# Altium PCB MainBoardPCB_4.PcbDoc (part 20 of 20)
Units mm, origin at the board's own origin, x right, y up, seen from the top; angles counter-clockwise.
Board outline 333.63 x 349.38 mm, 16 copper layers (L1, L2 (GND), L3 (Sign), L4 (GND), L5 (Sign), L6 (PWR/GND), L7(PWR/GND), L8 (Plane_GND), L9 (PWR/GND), L10 (PWR/GND), L11 (PWR/GND), L12 (Sign), L13 (GND), L14 (Sign), L15 (GND), L16), stack 2.502 mm thick; 2205 components, 1648 nets, 8314 pads, 3172 vias.
Unrouted connection lines stored in the file: 5141.
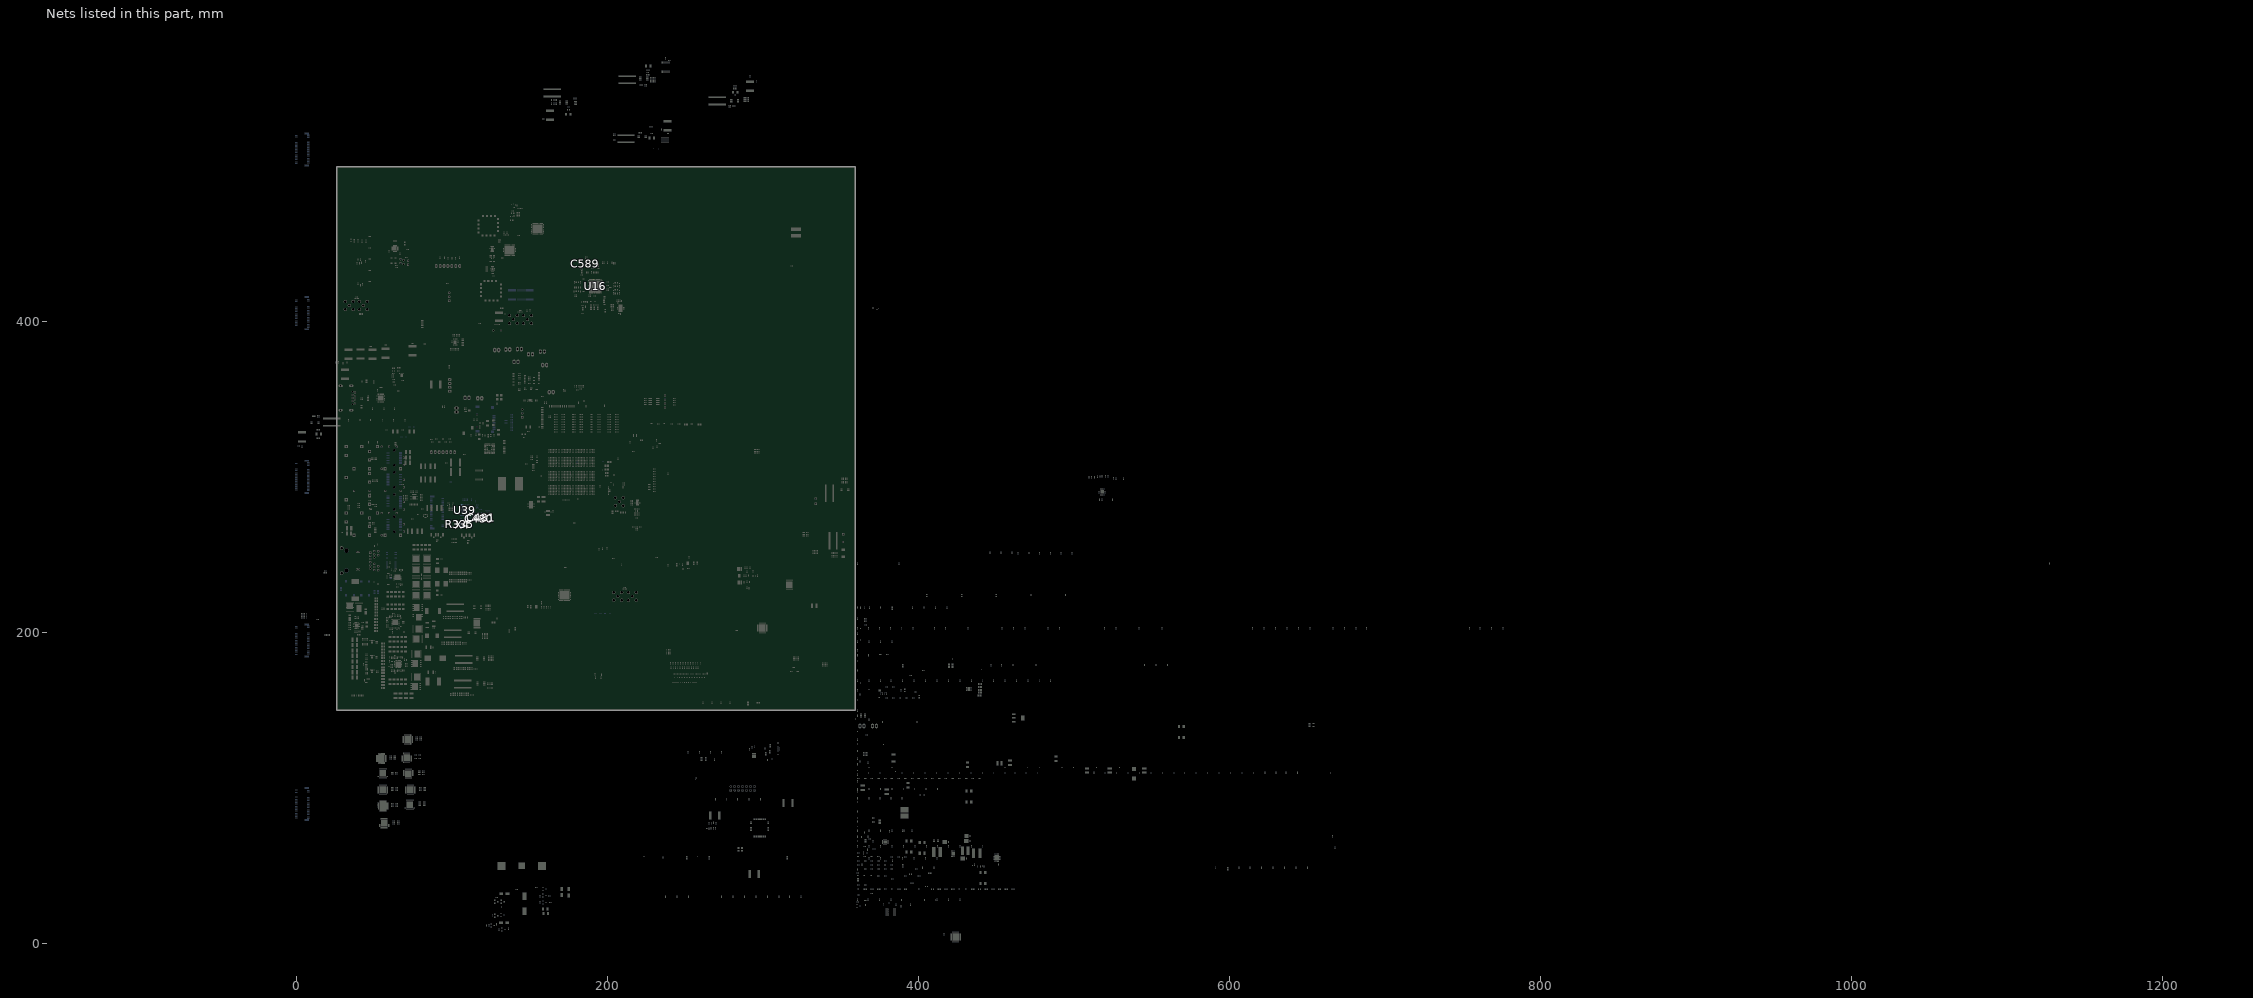
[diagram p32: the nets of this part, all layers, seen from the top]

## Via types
v1: diameter 0.5, hole 0.2, L1 to L16, tented both sides, 1153 vias
v2: diameter 0.5/0.35/0.35/0.35/0.35/0.35/0.35/0.35/0.35/0.35/0.35/0.35/0.35/0.35/0.35/0.5 (per signal layer), hole 0.2, L1 to L16, tented both sides, 548 vias
v3: diameter 0.5, hole 0.2, L1 to L16, 522 vias
v4: diameter 0.5/0.35/0.35/0.35/0.35/0.35/0.35/0.35/0.35/0.35/0.35/0.35/0.35/0.35/0.35/0.5 (per signal layer), hole 0.15, L1 to L16, tented both sides, 266 vias
v5: diameter 0.8, hole 0.4, L1 to L16, tented both sides, 164 vias
v6: diameter 0.35/0/0.35 (per signal layer), hole 0.127, L1 to L3 (Sign), tented both sides, 132 vias
v7: diameter 2.54, hole 1.02, L1 to L16, 125 vias
v8: diameter 1.4, hole 0.5, L1 to L16, tented both sides, 80 vias
v9: diameter 0.35, hole 0.127, L1 to L2 (GND), tented both sides, 36 vias
v10: diameter 0.4, hole 0.2, L1 to L16, 16 vias
v11: diameter 0.25, hole 0.2, L1 to L16, 16 vias
v12: diameter 5, hole 3, L1 to L16, 15 vias
v13: diameter 0.3, hole 0.2, L1 to L16, 15 vias
v14: diameter 0.45, hole 0.15, L1 to L16, 12 vias
v15: diameter 0.5/0.35/0.35/0.35/0.35/0.35/0.35/0.35/0.35/0.35/0.35/0.35/0.35/0.35/0.35/0.45 (per signal layer), hole 0.15, L1 to L16, tented both sides, 10 vias
v16: diameter 0.2/0/0.2 (per signal layer), hole 0.1, L1 to L3 (Sign), tented both sides, 9 vias
v17: diameter 0.4, hole 0.1, L1 to L16, 7 vias
v18: diameter 0.5, hole 0.2, L3 (Sign) to L6 (PWR/GND), tented both sides, 6 vias
v19: diameter 1.65, hole 1.65, L1 to L16, 6 vias
v20: diameter 1.15, hole 1.15, L1 to L16, 6 vias
v21: diameter 0.35/0/0.35 (per signal layer), hole 0.127, L14 (Sign) to L16, tented both sides, 5 vias
v22: diameter 0.2, hole 0.1, L1 to L16, 4 vias
v23: diameter 0.4, hole 0.2, L1 to L16, tented both sides, 2 vias
v24: diameter 0.4, hole 0.15, L1 to L16, 2 vias
v25: diameter 0.508, hole 0.127, L1 to L2 (GND), 2 vias
v26: diameter 0.508, hole 0.127, L2 (GND) to L3 (Sign), 2 vias
v27: diameter 0.5/0.35/0.35/0.35/0.35/0.35/0.35/0.35/0.35/0.35/0.35/0.35/0.35/0.35/0.35/0.5 (per signal layer), hole 0.15, L1 to L16, 2 vias
v28: diameter 0.35, hole 0.127, L3 (Sign) to L6 (PWR/GND), tented both sides, 2 vias
v29: diameter 5.5, hole 3.5, L1 to L16, 1 vias
v30: diameter 0.5/0.35/0.35/0.35/0.35/0.35/0.35/0.35/0.35/0.35/0.35/0.35/0.35/0.35/0.35/0.5 (per signal layer), hole 0.2, L1 to L16, 1 vias
v31: diameter 0.35/0.35/0.35 (per signal layer), hole 0.127, L1 to L3 (Sign), tented both sides, 1 vias
v32: diameter 0.45/0/0.45 (per signal layer), hole 0.15, L1 to L3 (Sign), tented both sides, 1 vias
v33: diameter 0.45/0/0.45 (per signal layer), hole 0.2, L14 (Sign) to L16, tented both sides, 1 vias
v34: diameter 0.35, hole 0.127, L2 (GND) to L3 (Sign), 1 vias
v35: diameter 0.35, hole 0.127, L1 to L2 (GND), 1 vias

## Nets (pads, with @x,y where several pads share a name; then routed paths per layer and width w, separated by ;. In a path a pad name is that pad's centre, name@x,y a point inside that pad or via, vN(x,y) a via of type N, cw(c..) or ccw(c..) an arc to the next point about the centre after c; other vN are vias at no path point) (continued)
X1: C481.2 R335.2 U39.14 X4.1
X2: C480.2 R335.1 U39.15 X4.3
XO_LMK05028_P: C589.2 U16.43
pads on no net: C558.4 D22.2 D28.1 J1_PCIE0. J1_PCIE0.56 J1_PCIE0.58 J1_PCIE1. J1_PCIE1.56 J1_PCIE1.58 J1_PCIE2. J1_PCIE2.56 J1_PCIE2.58 J1_PCIE3. J1_PCIE3.56 J1_PCIE3.58 J1_PCIE4. J1_PCIE4.56 J1_PCIE4.58 J14.3 J27. J27.5 J27.6 J27.7 J27.8 J27.11 J27.13 J27.17 J27.19 J27.20 J27.22 J27.23 J27.24 J27.25 J27.26 J27.28 J27.30 J27.32 J27.34 J27.36 J27.40 J27.42 J27.44 J27.46 J27.48 J27.56 J27.58 J27.59 J28.MH1 J28.MH2 J31. J31.1 J31.2 J31.3 J31.4 J31.5 J31.6 J31.7 J31.8 J31.9 J31.10 J31.11 J31.12 J31.13 J31.14 J31.15 J31.16 J31.17 J31.18 J31.19 J31.20 J31.21 J31.22 J31.23 J31.24 J31.25 J31.26 J31.27 J31.28 J31.29 J31.30 J31.31 J31.32 J31.33 J31.34 J31.35 J31.36 J31.37 J31.38 J31.39 J31.40 J31.41 J31.42 J31.43 J31.44 J31.45 J31.46 J31.47 J31.48 J31.49 J31.50 J31.51 J31.52 J31.53 J31.54 J31.55 J31.56 J31.57 J31.58 J31.59 J31.60 J31.61 J31.62 J31.63 J31.64 J31.65 J31.66 J31.67 J31.68 J31.69 J31.70 J31.71 J31.72 J31.73 J31.74 J31.75 J31.76 J31.77 J31.78 J31.79 J31.80 P12.11 R100.1 R100.2 R132.2 R133.2 R134.2 R135.2 R136.2 R137.2 R138.2 R141.2 R142.2 R145.2 R146.2 R147.2 R148.2 R151.2 R152.2 R455_1.1 R455_1.2 R456_1.1 R456_1.2 R458_1.1 R458_1.2 R460_1.1 R460_1.2 R462_1.1 R462_1.2 R464_1.1 R464_1.2 R475_1.1 R475_1.2 R476_1.1 R476_1.2 R477_1.1 R477_1.2 R478_1.1 R478_1.2 R479_1.1 R479_1.2 R480_1.1 R480_1.2 R492_1.1 R492_1.2 R493_1.1 R493_1.2 R494_1.1 R494_1.2 R495_1.1 R495_1.2 R496_1.1 R496_1.2 R497_1.1 R497_1.2 R500_1.1 R500_1.2 R501_1.1 R501_1.2 R502_1.1 R502_1.2 R503_1.1 R503_1.2 R504_1.1 R504_1.2 R505_1.1 R505_1.2 R508_1.1 R508_1.2 R509_1.1 R509_1.2 R510_1.1 R510_1.2 R511_1.1 R511_1.2 R512_1.1 R512_1.2 R513_1.1 R513_1.2 R516_1.1 R516_1.2 R517_1.1 R517_1.2 R518_1.1 R518_1.2 R519_1.1 R519_1.2 R520_1.1 R520_1.2 R521_1.1 R521_1.2 R654.1 R697_1.1 R697_1.2 R698_1.1 R698_1.2 R699_1.1 R699_1.2 R700_1.1 R700_1.2 R701_1.1 R701_1.2 R702_1.1 R702_1.2 R703_1.1 R703_1.2 R704_1.1 R704_1.2 R705_1.1 R705_1.2 R706_1.1 R706_1.2 R707_1.1 R707_1.2 R708_1.1 R708_1.2 R738_1.1 R738_1.2 R739_1.1 R739_1.2 R740_1.1 R740_1.2 R741_1.1 R741_1.2 R742_1.1 R742_1.2 R743_1.1 R743_1.2 R758_1.1 R758_1.2 R759_1.1 R759_1.2 R760_1.1 R760_1.2 R761_1.1 R761_1.2 R762_1.1 R762_1.2 R763_1.1 R763_1.2 R776.1 R777.1 T5. T6. T7. T8. T9. T10. T11. T12. T13. T14. T15. T16. T17. T18. T19. T20. T21.MH1 T21.MH2 T35. U1.A12 U1.A13 U1.A14 U1.A15 U1.A16 U1.A17 U1.A19 U1.AA8 U1.AA16 U1.AA17 U1.AA26 U1.AA30 U1.AB5 U1.AB6 U1.AB8 U1.AB16 U1.AB18 U1.AB19 U1.AB20 U1.AB21 U1.AB29 U1.AC7 U1.AC8 U1.AC13 U1.AC16 U1.AC17 U1.AC18 U1.AC19 U1.AD7 U1.AD16 U1.AD17 U1.AD19 U1.AE7 U1.AE10 U1.AE12 U1.AE17 U1.AE18 U1.AE19 U1.AF1 U1.AF2 U1.AF13 U1.AF15 U1.AF16 U1.AF17 U1.AF18 U1.AG3 U1.AG4 U1.AG5 U1.AG6 U1.AG8 U1.AG9 U1.AG14 U1.AG15 U1.AG16 U1.AG18 U1.AG19 U1.AH1 U1.AH2 U1.AH3 U1.AH4 U1.AH6 U1.AH7 U1.AH8 U1.AH14 U1.AH16 U1.AH17 U1.AH18 U1.AJ6 U1.AJ7 U1.AJ14 U1.AJ15 U1.AJ16 U1.AJ17 U1.AJ27 U1.AK12 U1.AK14 U1.AK15 U1.AK16 U1.AK17 U1.AK18 U1.B12 U1.B14 U1.B15 U1.B16 U1.B19 U1.C12 U1.C13 U1.C14 U1.C16 U1.C17 U1.D12 U1.D14 U1.D15 U1.D16 U1.D17 U1.E12 U1.E13 U1.E14 U1.E15 U1.E17 U1.F12 U1.F13 U1.F15 U1.F16 U1.G13 U1.G14 U1.G15 U1.G16 U1.H12 U1.H13 U1.H14 U1.H16 U1.J12 U1.J14 U1.J15 U1.J16 U1.K11 U1.K13 U1.K14 U1.K15 U1.L14 U1.L15 U1.L25 U1.L26 U1.W9 U1.W10 U1.W26 U1.W27 U1.Y9 U1.Y27 U1.Y29 U1.Y30 U4.11 U5.11 U8.T4 U9.T4 U10.T4 U11.T4 U12.12 U12.13 U12.15 U12.16 U12.18 U12.19 U12.21 U12.22 U12.24 U12.25 U12.27 U12.28 U12.50 U13.9 U13.10 U13.12 U13.13 U13.15 U13.16 U13.18 U13.19 U13.21 U13.22 U13.24 U13.25 U13.27 U13.28 U13.30 U13.31 U13.33 U13.34 U13.42 U13.43 U14.42 U14.43 U16.5 U16.6 U16.10 U16.11 U16.18 U18.A3 U26_SPI_bridge2.14 U28_SPI_bridge2.12 U28_SPI_bridge2.13 U28_SPI_bridge2.14 U30.6 U30.7 U30.8 U31.3 U31.4 U31.8 U31.13 U31.14 U31.15 U31.16 U32.8 U32.13 U32.14 U32.15 U32.16 U33.7 U35_I2C_Expander1.7 U35_I2C_Expander1.10 U35_I2C_Expander1_1.1 U35_I2C_Expander1_1.2 U35_I2C_Expander1_1.3 U35_I2C_Expander1_1.4 U35_I2C_Expander1_1.5 U35_I2C_Expander1_1.6 U35_I2C_Expander1_1.7 U35_I2C_Expander1_1.8 U35_I2C_Expander1_1.9 U35_I2C_Expander1_1.10 U35_I2C_Expander1_1.11 U35_I2C_Expander1_1.12 U35_I2C_Expander1_1.13 U35_I2C_Expander1_1.14 U35_I2C_Expander1_1.15 U35_I2C_Expander1_1.16 U35_I2C_Expander1_1.17 U35_I2C_Expander1_1.18 U35_I2C_Expander1_1.19 U35_I2C_Expander1_1.20 U35_I2C_Expander1_1.21 U35_I2C_Expander1_1.22 U35_I2C_Expander1_1.23 U35_I2C_Expander1_1.24 U35_I2C_Expander1_1.25 U35_I2C_Expander1_1.26 U35_I2C_Expander1_1.27 U35_I2C_Expander1_1.28 U35_I2C_Expander1_1.29 U35_I2C_Expander2.7 U35_I2C_Expander2.10 U35_I2C_Expander2_1.1 U35_I2C_Expander2_1.2 U35_I2C_Expander2_1.3 U35_I2C_Expander2_1.4 U35_I2C_Expander2_1.5 U35_I2C_Expander2_1.6 U35_I2C_Expander2_1.7 U35_I2C_Expander2_1.8 U35_I2C_Expander2_1.9 U35_I2C_Expander2_1.10 U35_I2C_Expander2_1.11 U35_I2C_Expander2_1.12 U35_I2C_Expander2_1.13 U35_I2C_Expander2_1.14 U35_I2C_Expander2_1.15 U35_I2C_Expander2_1.16 U35_I2C_Expander2_1.17 U35_I2C_Expander2_1.18 U35_I2C_Expander2_1.19 U35_I2C_Expander2_1.20 U35_I2C_Expander2_1.21 U35_I2C_Expander2_1.22 U35_I2C_Expander2_1.23 U35_I2C_Expander2_1.24 U35_I2C_Expander2_1.25 U35_I2C_Expander2_1.26 U35_I2C_Expander2_1.27 U35_I2C_Expander2_1.28 U35_I2C_Expander2_1.29 U35_I2C_Expander3.7 U35_I2C_Expander3.10 U35_I2C_Expander3_1.1 U35_I2C_Expander3_1.2 U35_I2C_Expander3_1.3 U35_I2C_Expander3_1.4 U35_I2C_Expander3_1.5 U35_I2C_Expander3_1.6 U35_I2C_Expander3_1.7 U35_I2C_Expander3_1.8 U35_I2C_Expander3_1.9 U35_I2C_Expander3_1.10 U35_I2C_Expander3_1.11 U35_I2C_Expander3_1.12 U35_I2C_Expander3_1.13 U35_I2C_Expander3_1.14 U35_I2C_Expander3_1.15 U35_I2C_Expander3_1.16 U35_I2C_Expander3_1.17 U35_I2C_Expander3_1.18 U35_I2C_Expander3_1.19 U35_I2C_Expander3_1.20 U35_I2C_Expander3_1.21 U35_I2C_Expander3_1.22 U35_I2C_Expander3_1.23 U35_I2C_Expander3_1.24 U35_I2C_Expander3_1.25 U35_I2C_Expander3_1.26 U35_I2C_Expander3_1.27 U35_I2C_Expander3_1.28 U35_I2C_Expander3_1.29 U35_I2C_Expander?.1 U35_I2C_Expander?.2 U35_I2C_Expander?.3 U35_I2C_Expander?.4 U35_I2C_Expander?.5 U35_I2C_Expander?.6 U35_I2C_Expander?.7 U35_I2C_Expander?.8 U35_I2C_Expander?.9 U35_I2C_Expander?.10 U35_I2C_Expander?.11 U35_I2C_Expander?.12 U35_I2C_Expander?.13 U35_I2C_Expander?.14 U35_I2C_Expander?.15 U35_I2C_Expander?.16 U35_I2C_Expander?.17 U35_I2C_Expander?.18 U35_I2C_Expander?.19 U35_I2C_Expander?.20 U35_I2C_Expander?.21 U35_I2C_Expander?.22 U35_I2C_Expander?.23 U35_I2C_Expander?.24 U35_I2C_Expander?.25 U35_I2C_Expander?.26 U35_I2C_Expander?.27 U35_I2C_Expander?.28 U35_I2C_Expander?.29 U35_I2C_Expander_10.1 U35_I2C_Expander_10.2 U35_I2C_Expander_10.3 U35_I2C_Expander_10.4 U35_I2C_Expander_10.5 U35_I2C_Expander_10.6 U35_I2C_Expander_10.7 U35_I2C_Expander_10.8 U35_I2C_Expander_10.9 U35_I2C_Expander_10.10 U35_I2C_Expander_10.11 U35_I2C_Expander_10.12 U35_I2C_Expander_10.13 U35_I2C_Expander_10.14 U35_I2C_Expander_10.15 U35_I2C_Expander_10.16 U35_I2C_Expander_10.17 U35_I2C_Expander_10.18 U35_I2C_Expander_10.19 U35_I2C_Expander_10.20 U35_I2C_Expander_10.21 U35_I2C_Expander_10.22 U35_I2C_Expander_10.23 U35_I2C_Expander_10.24 U35_I2C_Expander_10.25 U35_I2C_Expander_10.26 U35_I2C_Expander_10.27 U35_I2C_Expander_10.28 U35_I2C_Expander_10.29 U35_I2C_Expander_11.1 U35_I2C_Expander_11.2 U35_I2C_Expander_11.3 U35_I2C_Expander_11.4 U35_I2C_Expander_11.5 U35_I2C_Expander_11.6 U35_I2C_Expander_11.7 U35_I2C_Expander_11.8 U35_I2C_Expander_11.9 U35_I2C_Expander_11.10 U35_I2C_Expander_11.11 U35_I2C_Expander_11.12 U35_I2C_Expander_11.13 U35_I2C_Expander_11.14 U35_I2C_Expander_11.15 U35_I2C_Expander_11.16 U35_I2C_Expander_11.17 U35_I2C_Expander_11.18 U35_I2C_Expander_11.19 U35_I2C_Expander_11.20 U35_I2C_Expander_11.21 U35_I2C_Expander_11.22 U35_I2C_Expander_11.23 U35_I2C_Expander_11.24 U35_I2C_Expander_11.25 U35_I2C_Expander_11.26 U35_I2C_Expander_11.27 U35_I2C_Expander_11.28 U35_I2C_Expander_11.29 U35_I2C_Expander_12.1 U35_I2C_Expander_12.2 U35_I2C_Expander_12.3 U35_I2C_Expander_12.4 U35_I2C_Expander_12.5 U35_I2C_Expander_12.6 U35_I2C_Expander_12.7 U35_I2C_Expander_12.8 U35_I2C_Expander_12.9 U35_I2C_Expander_12.10 U35_I2C_Expander_12.11 U35_I2C_Expander_12.12 U35_I2C_Expander_12.13 U35_I2C_Expander_12.14 U35_I2C_Expander_12.15 U35_I2C_Expander_12.16 U35_I2C_Expander_12.17 U35_I2C_Expander_12.18 U35_I2C_Expander_12.19 U35_I2C_Expander_12.20 U35_I2C_Expander_12.21 U35_I2C_Expander_12.22 U35_I2C_Expander_12.23 U35_I2C_Expander_12.24 U35_I2C_Expander_12.25 U35_I2C_Expander_12.26 U35_I2C_Expander_12.27 U35_I2C_Expander_12.28 U35_I2C_Expander_12.29 U35_I2C_Expander_13.1 U35_I2C_Expander_13.2 U35_I2C_Expander_13.3 U35_I2C_Expander_13.4 U35_I2C_Expander_13.5 U35_I2C_Expander_13.6 U35_I2C_Expander_13.7 U35_I2C_Expander_13.8 U35_I2C_Expander_13.9 U35_I2C_Expander_13.10 U35_I2C_Expander_13.11 U35_I2C_Expander_13.12 U35_I2C_Expander_13.13 U35_I2C_Expander_13.14 U35_I2C_Expander_13.15 U35_I2C_Expander_13.16 U35_I2C_Expander_13.17 U35_I2C_Expander_13.18 U35_I2C_Expander_13.19 U35_I2C_Expander_13.20 U35_I2C_Expander_13.21 U35_I2C_Expander_13.22 U35_I2C_Expander_13.23 U35_I2C_Expander_13.24 U35_I2C_Expander_13.25 U35_I2C_Expander_13.26 U35_I2C_Expander_13.27 U35_I2C_Expander_13.28 U35_I2C_Expander_13.29 U35_I2C_Expander_14.1 U35_I2C_Expander_14.2 U35_I2C_Expander_14.3 U35_I2C_Expander_14.4 U35_I2C_Expander_14.5 U35_I2C_Expander_14.6 U35_I2C_Expander_14.7 U35_I2C_Expander_14.8 U35_I2C_Expander_14.9 U35_I2C_Expander_14.10 U35_I2C_Expander_14.11 U35_I2C_Expander_14.12 U35_I2C_Expander_14.13 U35_I2C_Expander_14.14 U35_I2C_Expander_14.15 U35_I2C_Expander_14.16 U35_I2C_Expander_14.17 U35_I2C_Expander_14.18 U35_I2C_Expander_14.19 U35_I2C_Expander_14.20 U35_I2C_Expander_14.21 U35_I2C_Expander_14.22 U35_I2C_Expander_14.23 U35_I2C_Expander_14.24 U35_I2C_Expander_14.25 U35_I2C_Expander_14.26 U35_I2C_Expander_14.27 U35_I2C_Expander_14.28 U35_I2C_Expander_14.29 U35_I2C_Expander_16.7 U35_I2C_Expander_16.10 U35_I2C_Expander_16_1.1 U35_I2C_Expander_16_1.2 U35_I2C_Expander_16_1.3 U35_I2C_Expander_16_1.4 U35_I2C_Expander_16_1.5 U35_I2C_Expander_16_1.6 U35_I2C_Expander_16_1.7 U35_I2C_Expander_16_1.8 U35_I2C_Expander_16_1.9 U35_I2C_Expander_16_1.10 U35_I2C_Expander_16_1.11 U35_I2C_Expander_16_1.12 U35_I2C_Expander_16_1.13 U35_I2C_Expander_16_1.14 U35_I2C_Expander_16_1.15 U35_I2C_Expander_16_1.16 U35_I2C_Expander_16_1.17 U35_I2C_Expander_16_1.18 U35_I2C_Expander_16_1.19 U35_I2C_Expander_16_1.20 U35_I2C_Expander_16_1.21 U35_I2C_Expander_16_1.22 U35_I2C_Expander_16_1.23 U35_I2C_Expander_16_1.24 U35_I2C_Expander_16_1.25 U35_I2C_Expander_16_1.26 U35_I2C_Expander_16_1.27 U35_I2C_Expander_16_1.28 U35_I2C_Expander_16_1.29 U39.18 U39.25 U39.26 U39.29 U39.32 U39.37 U39.38 U39.40 U40.6 U41.A1 U41.A2 U41.A7 U41.A8 U41.A9 U41.A10 U41.A11 U41.A12 U41.A13 U41.A14 U41.B1 U41.B7 U41.B8 U41.B9 U41.B10 U41.B11 U41.B12 U41.B13 U41.B14 U41.C1 U41.C3 U41.C5 U41.C7 U41.C8 U41.C9 U41.C10 U41.C11 U41.C12 U41.C13 U41.C14 U41.D1 U41.D2 U41.D3 U41.D4 U41.D12 U41.D13 U41.D14 U41.E1 U41.E2 U41.E3 U41.E5 U41.E8 U41.E9 U41.E10 U41.E12 U41.E13 U41.E14 U41.F1 U41.F2 U41.F3 U41.F10 U41.F12 U41.F13 U41.F14 U41.G1 U41.G2 U41.G3 U41.G10 U41.G12 U41.G13 U41.G14 U41.H1 U41.H2 U41.H3 U41.H5 U41.H12 U41.H13 U41.H14 U41.J1 U41.J2 U41.J3 U41.J12 U41.J13 U41.J14 U41.K1 U41.K2 U41.K3 U41.K6 U41.K7 U41.K10 U41.K12 U41.K13 U41.K14 U41.L1 U41.L2 U41.L3 U41.L12 U41.L13 U41.L14 U41.M1 U41.M2 U41.M3 U41.M7 U41.M8 U41.M9 U41.M10 U41.M11 U41.M12 U41.M13 U41.M14 U41.N1 U41.N3 U41.N6 U41.N7 U41.N8 U41.N9 U41.N10 U41.N11 U41.N12 U41.N13 U41.N14 U41.P1 U41.P2 U41.P7 U41.P8 U41.P9 U41.P10 U41.P11 U41.P12 U41.P13 U41.P14 U42.6 U44.8 U44.9 U45.12 U45.15 U45.16 U46.A3 U46.B3 U46.C4 U47.E2 U47.E4 U48.11 U55.22 U55.28 U55.29 U55.30 U55.32 U55.33 U55.34 U55.36 U55.43 U55.44 U55.45 U55.46 U55.53 U55.54 U55.55 U55.57 U55.58 U55.59 U55.60 U57.11 U57.12 U58.10 U58.11 U59_5V_to_3V3_for_FTDI.6 U59_U_5V_to_3V31.6 U59_U_5V_to_3V32.6 U59_U_5V_to_3V33.6 U60.8 U63.5 U65.1 U69.8 U73.3 U78.3 U78.4 U79.5 U79.6 U79.11 U79.12
copper on no net: | length 221
  L1 w0.116: 206.324,342.392 v4(206.728,342.796) ; 211.541,342.801 211.938,342.405 v6(211.938,342.402) ; 370.718,242.339 v6(371.408,242.339) ; 370.955,237.947 v2(371.442,238.434) ; 374.352,239.977 v2(374.839,240.464) ; 374.809,249.091 v3(375.296,249.579) ; 376.803,243.901 v6(377.29,244.389)
  L1 w0.254: 57.596,118.886 58.238,118.886 59.388,117.736 60.812,117.736 61.109,118.033 61.109,118.455 61.164,118.511 ; 57.596,119.536 57.601,119.542 v3(59.046,119.542) ; 57.596,120.186 57.971,120.186 59.171,121.386 60.754,121.386 61.168,120.973 61.168,120.592 ; 58.521,98.666 59.206,98.666 60.356,97.516 61.94,97.516 62.24,97.816 62.24,98.214 62.29,98.264 64.177,98.264 64.179,98.266 ; 58.521,99.316 v3(60.139,99.316) ; 58.521,99.966 59.156,99.966 60.356,101.166 61.94,101.166 62.29,100.816 62.29,100.364 64.177,100.364 64.179,100.366 ; 58.521,109.332 59.506,109.332 60.7,108.138 61.804,108.138 62.004,108.338 62.004,108.972 63.855,108.973 ; 58.521,109.982 58.523,109.979 v3(59.839,109.979) ; 58.521,110.632 59.504,110.632 60.754,111.882 61.613,111.882 62.004,111.49 62.004,111.006 63.855,111.006 ; 58.636,88.333 59.538,88.333 60.604,87.268 61.854,87.268 62.148,87.562 62.148,87.962 64.179,87.962 ; 58.636,88.983 v3(60.172,88.983) ; 58.636,89.633 59.404,89.633 60.604,90.833 61.891,90.833 62.148,90.577 62.148,90.027 64.179,90.027 ; 59.296,77.163 60.071,77.163 61.371,75.863 62.884,75.863 63.088,76.067 63.088,76.815 64.28,76.815 64.289,76.806 65.079,76.806 ; 59.296,77.813 59.305,77.822 v3(60.822,77.822) ; 59.296,78.463 60.026,78.463 61.226,79.663 62.884,79.663 63.09,79.457 63.09,78.813 64.28,78.813 64.289,78.803 65.079,78.803 ; 61.136,118.483 62.941,118.483 62.976,118.519 ; 61.168,119.548 61.169,119.549 v3(62.133,119.549) ; 61.168,120.6 62.98,120.6 ; 61.756,119.556 62.98,119.556 ; 62.004,109.979 v3(62.985,109.979) 63.855,109.979 ; 62.148,88.983 v3(63.185,88.983) 64.179,88.983 ; 62.29,99.316 62.323,99.283 v3(63.181,99.283) 63.199,99.301 64.162,99.301 64.179,99.319 ; 63.09,77.822 v3(64.167,77.822) 64.172,77.818 65.075,77.818 65.079,77.813 ; 73.817,119.263 74.722,119.263 75.872,118.113 76.981,118.113 77.254,118.386 77.254,118.89 78.973,118.89 ; 73.817,119.913 73.865,119.961 73.89,119.937 v3(75.319,119.937) ; 73.817,120.563 74.402,120.563 75.772,121.934 76.832,121.934 77.181,121.585 77.181,121.179 77.253,121.107 78.971,121.107 ; 74.603,131.106 75.507,131.106 76.35,130.264 77.64,130.264 77.831,130.455 77.831,130.791 79.644,130.791 ; 74.603,131.756 v3(75.8,131.756) ; 74.603,132.406 75.378,132.406 76.26,133.288 77.682,133.288 77.831,133.139 77.831,132.741 79.644,132.741 ; 74.915,109.182 76.205,109.182 77.505,107.882 79.043,107.882 79.393,108.232 79.393,108.682 81.208,108.682 ; 74.915,109.832 74.936,109.811 v3(76.981,109.811) ; 74.915,110.482 76.37,110.482 77.505,111.618 79.043,111.618 79.367,111.293 79.367,110.841 79.392,110.815 81.208,110.815 ; 75.88,89.078 76.655,89.078 78.061,87.672 79.461,87.672 79.713,87.924 79.713,88.634 79.716,88.637 80.956,88.637 80.959,88.64 81.709,88.64 ; 75.88,89.728 75.886,89.734 v3(77.505,89.734) ; 75.88,90.378 76.621,90.378 76.655,90.344 78.264,91.953 79.122,91.953 79.603,91.472 79.603,90.944 79.713,90.833 81.708,90.833 ; 76.167,98.666 77.218,98.666 78.412,97.472 80.004,97.472 80.154,97.622 80.154,98.272 82.247,98.272 ; 76.167,99.316 76.183,99.3 v3(77.955,99.3) ; 76.167,99.966 77.218,99.966 78.418,101.166 79.797,101.166 80.155,100.807 80.155,100.316 82.247,100.316 ; 77.253,120.002 v3(78.031,120.002) 78.971,120.002 ; 77.831,131.756 v3(78.733,131.756) 79.644,131.756 ; 79.392,109.79 79.413,109.811 v3(80.342,109.811) 80.352,109.801 81.198,109.801 81.208,109.79 ; v3@80.776,89.737 79.717,89.737 79.713,89.74 80.776,89.74 v3(80.778,89.739) ; v3@80.777,89.736 81.706,89.736 81.709,89.733 ; 82.247,99.316 82.245,99.314 81.356,99.314 v3(81.354,99.312) ; v3(81.354,99.312) 80.167,99.312 80.154,99.3 80.162,99.308 81.35,99.308 v3(81.354,99.312)
  L1 w0.5: v1(42.597,17.328) 42.597,18.415 ; v1(42.597,20.128) 42.597,21.215 ; 43.145,18.415 v1(43.145,19.502) ; 43.145,21.215 v1(43.145,22.302) ; v1(43.694,17.328) 43.694,18.415 ; v1(43.694,20.128) 43.694,21.215 ; 44.25,18.415 v1(44.25,19.502) ; 44.25,21.215 v1(44.25,22.302) ; v1(44.799,17.328) 44.799,18.415 ; v1(44.799,20.128) 44.799,21.215
  L5 (Sign) w0.116: v28(371.685,243.799) v28(372.706,242.779)
  L3 (Sign) w0.092: 212.405,343.017 v18(212.801,342.621)
  L14 (Sign) w0.254: v3(59.046,119.542) 62.127,119.542 v3(62.133,119.549) ; v3(59.839,109.979) v3(62.985,109.979) ; v3(60.139,99.316) 60.172,99.283 v3(63.181,99.283) ; v3(60.172,88.983) v3(63.185,88.983) ; v3(60.822,77.822) v3(64.167,77.822) ; v3(75.319,119.937) 77.228,119.937 77.253,119.961 ; v3(75.8,131.756) v3(78.733,131.756) ; v3(76.981,109.811) v3(80.342,109.811) ; 77.236,120.002 v3(78.031,120.002) ; v3(77.505,89.734) 80.774,89.734 v3(80.778,89.739) ; v3(77.955,99.3) 77.967,99.312 v3(81.354,99.312)
  other v3: 54.771,75.513 55.871,75.513 56.971,75.513 58.071,75.513 54.771,76.613 55.871,76.613 56.971,76.613 58.071,76.613 54.771,77.713 55.871,77.713 56.971,77.713 58.071,77.713 54.771,78.813 55.871,78.813 56.971,78.813 58.071,78.813 54.111,86.683 55.211,86.683 56.311,86.683 57.411,86.683 71.355,87.428 72.455,87.428 73.555,87.428 74.655,87.428 54.111,87.783 55.211,87.783 56.311,87.783 57.411,87.783 71.355,88.528 72.455,88.528 73.555,88.528 74.655,88.528 54.111,88.883 55.211,88.883 56.311,88.883 57.411,88.883 71.355,89.628 72.455,89.628 73.555,89.628 74.655,89.628 54.111,89.983 55.211,89.983 56.311,89.983 57.411,89.983 71.355,90.728 72.455,90.728 73.555,90.728 74.655,90.728 53.996,97.016 55.096,97.016 56.196,97.016 57.296,97.016 71.642,97.016 72.742,97.016 73.842,97.016 74.942,97.016 53.996,98.116 55.096,98.116 56.196,98.116 57.296,98.116 71.642,98.116 72.742,98.116 73.842,98.116 74.942,98.116 53.996,99.216 55.096,99.216 56.196,99.216 57.296,99.216 71.642,99.216 72.742,99.216 73.842,99.216 74.942,99.216 53.996,100.316 55.096,100.316 56.196,100.316 57.296,100.316 71.642,100.316 72.742,100.316 73.842,100.316 74.942,100.316 70.39,107.532 71.49,107.532 72.59,107.532 73.69,107.532 53.996,107.682 55.096,107.682 56.196,107.682 57.296,107.682 70.39,108.632 71.49,108.632 72.59,108.632 73.69,108.632 53.996,108.782 55.096,108.782 56.196,108.782 57.296,108.782 70.39,109.732 71.49,109.732 72.59,109.732 73.69,109.732 53.996,109.882 55.096,109.882 56.196,109.882 57.296,109.882 70.39,110.832 71.49,110.832 72.59,110.832 73.69,110.832 53.996,110.982 55.096,110.982 56.196,110.982 57.296,110.982 53.071,117.236 54.171,117.236 55.271,117.236 56.371,117.236 69.292,117.613 70.392,117.613 71.492,117.613 72.592,117.613 53.071,118.336 54.171,118.336 55.271,118.336 56.371,118.336 69.292,118.713 70.392,118.713 71.492,118.713 72.592,118.713 53.071,119.436 54.171,119.436 55.271,119.436 56.371,119.436 69.292,119.813 70.392,119.813 71.492,119.813 72.592,119.813 53.071,120.536 54.171,120.536 55.271,120.536 56.371,120.536 69.292,120.913 70.392,120.913 71.492,120.913 72.592,120.913 70.078,129.456 71.178,129.456 72.278,129.456 73.378,129.456 70.078,130.556 71.178,130.556 72.278,130.556 73.378,130.556 70.078,131.656 71.178,131.656 72.278,131.656 73.378,131.656 70.078,132.756 71.178,132.756 72.278,132.756 73.378,132.756
  other v4: 195.377,344.081
  other v7: 365.925,19.431 402.272,19.914 371.297,22.606 370.802,28.854 377.863,29.273 385.229,29.273 392.595,29.273 399.961,29.273 414.693,29.273 421.615,29.273 428.981,29.273 436.347,29.273 443.713,29.273 451.066,29.273 458.432,29.273 465.798,29.273 473.164,29.273 480.085,29.273 487.451,29.273 494.817,29.273 502.183,29.273 509.549,29.273 516.915,29.273 524.281,29.273 531.635,29.273 539.001,29.273 408.648,29.489 465.798,37.998 473.164,37.998 379.324,59.372 387.007,64.668 441.947,64.834 556.387,73.393 580.504,73.393 604.888,73.393 627.99,73.393 651.104,73.393 674.205,73.393 697.319,73.393 720.42,73.393 743.534,73.393 766.635,73.393 362.636,74.905 560.438,83.629 585.076,83.629 609.956,83.629 633.578,83.629 657.187,83.629 680.809,83.629 704.418,83.629 728.04,83.629 751.662,83.629 775.271,83.629 417.716,94.221 387.769,95.377 521.818,103.632 438.048,104.102 463.182,104.102 488.328,104.102 513.207,104.102 500.431,105.664 506.4,116.599 396.733,117.5 363.131,151.397 370.497,151.397 392.608,192.621 399.974,192.621 407.34,192.621 414.706,192.621 422.059,192.621 429.425,192.621 436.791,192.621 405.308,201.346 427.152,201.346 441.452,201.346 448.818,201.346 478.282,201.346 536.715,201.346 551.447,201.346 609.879,201.346 661.441,201.346 362.636,232.181 387.007,232.181 766.166,242.418 792.582,242.418 818.985,242.418 845.401,242.418 871.804,242.418 898.22,242.418 923.353,242.418 949.769,242.418 976.173,242.418 1002.322,242.418 1028.738,242.418 1053.871,242.418 1079.017,242.418 1104.151,242.418 1155.967,242.418 1181.1,242.418 1206.233,242.418 1231.379,242.418 362.636,351.409 387.261,351.409 411.899,351.409 436.524,351.409 362.636,361.645 387.769,361.645 412.915,361.645 362.636,371.881 240.182,388.887 235.217,390.855 240.805,395.199 258.966,398.031 247.282,398.082 231.61,398.196 253.441,398.64 239.789,400.736 231.318,402.933 254.734,404 247.688,404.228 231.546,408.013 238.938,408.292 262.179,409.651 250.114,409.873 256.083,410.096
  other v31: 375.296,249.579

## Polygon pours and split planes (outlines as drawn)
CSP on L1 "L1-CSP" (solid, pour order 279): 35.344,235.28 43.258,235.28 45.949,232.589 45.949,230.226 44.005,228.282 36.106,228.282 34.023,230.365 34.023,234.036 35.242,235.255
no net on L1 "L1-No Net" (solid, pour order 269): 91.618,222.154
12V_HiSpeed on L1 "L1-3V3_RAIL" (solid, pour order 267): 101.724,216.814 108.378,216.814 108.938,217.374 108.938,219.836 107.743,221.031 96.275,221.031 94.866,219.621 94.866,217.233 95.272,216.827 101.787,216.827
5V_RAIL on L1 "L1-3V3_RAIL" (solid, pour order 263): 100.266,199.987 106.921,199.987 107.481,200.546 107.481,203.009 106.286,204.203 94.818,204.203 93.408,202.794 93.408,200.406 93.815,200 100.33,200
RAM_Vcc1V2 on L1 "L1-3V3_RAIL" (solid, pour order 261): 106.536,167.665 113.19,167.665 113.75,168.225 113.75,170.687 112.555,171.882 101.087,171.882 99.678,170.472 99.678,168.084 100.084,167.678 106.599,167.678
3V3_RAIL on L1 "L1-3V3_RAIL" (solid, pour order 251): 107.391,183.528 114.046,183.528 114.605,184.087 114.605,186.55 113.411,187.744 101.943,187.744 100.533,186.334 100.533,183.947 100.94,183.54 107.455,183.54
Vout_5V@10A_INA on L1 "L1-Vout_5V@10A_INA" (solid, pour order 249): 92.405,200.584 94.297,198.691 107.455,198.691 110.045,196.101 110.045,193.205 109.828,192.987 89.918,192.987 87.816,195.089 87.816,199.136 89.264,200.584
Vout2_1 on L1 "L1-Vout2_1" (solid, pour order 247): 91.63,172.441 93.398,172.441 100.103,165.735 113.817,165.735 115.595,163.957 115.595,160.909 114.91,160.223 114.91,160.147 114.14,160.147 93.738,160.146 89.599,164.285 89.599,171.501 90.538,172.441
Vout1_1 on L1 "L1-Vout1_1" (solid, pour order 243): 96.208,186.85 101.498,181.559 113.602,181.559 114.579,180.581 114.579,179.317 116.187,179.317 117.615,177.889 117.615,176.949 117.516,176.851 93.685,176.851 90.081,180.454 90.081,185.039 91.892,186.85
Vout1_2 on L1 "L1-Vout1_2" (solid, pour order 239): 92.926,217.589 95.618,214.897 108.372,214.897 111.443,211.826 111.443,210.338 110.605,209.5 92.239,209.5 88.816,212.924 88.816,216.209 90.195,217.589
PWR_OUT_20V on L1 "L1-PWR_OUT_20V" (solid, pour order 235): 48.822,193.927 48.683,193.788 48.683,190.731 49.716,189.698 50.563,189.698 50.931,190.066 50.931,192.373 49.378,193.926 48.835,193.926
PWR_OUT_20V on L1 "L1-PWR_OUT_20V 1" (solid, pour order 233): 48.822,194.039 48.683,194.179 48.683,197.235 49.716,198.269 50.563,198.269 50.931,197.901 50.931,195.593 49.378,194.041 48.835,194.041
Vout_2_Selector on L1 "L1-Vout_2_Selector" (solid, pour order 231): 48.532,193.927 48.671,193.788 48.671,190.731 47.638,189.698 46.792,189.698 46.424,190.066 46.424,192.373 47.976,193.926 48.519,193.926
Battery_PWR on L1 "L1-Battery_PWR" (solid, pour order 229): 48.532,194.039 48.671,194.179 48.671,197.235 47.638,198.269 46.792,198.269 46.424,197.901 46.424,195.593 47.976,194.041 48.519,194.041
Power2_In_CM on L1 "L1-Power2_In_CM" (solid, pour order 227): 45.733,178.917 45.472,179.178 45.202,179.178 45.075,179.051 45.075,177.137 45.288,176.924 45.288,176.32 45.473,176.136 46.943,176.136 47.123,175.943 48.009,175.057 48.552,175.057 48.565,175.056 48.704,175.195 48.704,178.252 47.671,179.285 46.825,179.285 46.456,178.917
Power1_In_CM on L1 "L1-Power1_In_CM" (solid, pour order 225): 46.038,172.167 45.337,172.868 45.337,173.437 45.739,173.839 46.878,173.839 46.892,173.825 48.009,174.942 48.552,174.942 48.565,174.943 48.704,174.804 48.704,171.747 48.636,171.679 48.636,170.464 47.561,169.389 45.822,169.389 45.809,169.402 45.809,169.788 46.038,170.017
Vout_1_Selector on L1 "L1-Vout_1_Selector" (solid, pour order 223): 48.855,175.056 48.716,175.195 48.716,178.252 49.749,179.285 50.595,179.285 50.964,178.917 50.964,176.61 49.411,175.057 48.868,175.057
Vout_1_Selector on L1 "L1-Vout_1_Selector 1" (solid, pour order 221): 48.855,174.943 48.716,174.804 48.716,171.747 49.749,170.714 50.595,170.714 50.964,171.082 50.964,173.389 49.411,174.942 48.868,174.942
Vout_2_Selector on L1 "L1-Vout_2_Selector 1" (solid, pour order 219): 48.855,184.265 48.716,184.126 48.716,181.069 49.749,180.036 50.595,180.036 50.964,180.404 50.964,182.711 49.411,184.264 48.868,184.264
Vout_2_Selector on L1 "L1-Vout_2_Selector 2" (solid, pour order 217): 48.855,184.378 48.716,184.517 48.716,187.574 49.749,188.607 50.595,188.607 50.964,188.239 50.964,185.932 49.411,184.379 48.868,184.379
Vout_1_Selector on L1 "L1-Vout_1_Selector 2" (solid, pour order 215): 48.565,184.265 48.704,184.126 48.704,181.069 47.671,180.036 46.825,180.036 46.456,180.404 46.456,182.711 48.009,184.264 48.552,184.264
CSN on L1 "L1-CSN" (solid, pour order 213): 48.565,184.378 48.704,184.517 48.704,187.574 47.671,188.607 46.825,188.607 46.456,188.239 46.456,185.932 48.009,184.379 48.552,184.379
NetC693_1 on L1 "L1-NetC693_1" (solid, pour order 203): 35.331,225.234 31.229,221.132 31.229,215.252 32.029,214.452 37.211,214.452 38.544,215.786 38.544,217.276 38.909,217.64 42.862,217.64 42.862,223.444 41.072,225.234
SW2_1 on L1 "L1-SW2_1" (solid, pour order 199): 81.298,174.135 83.515,176.352 85.649,176.352 86.39,175.611 86.39,173.63 88.405,171.615 88.405,163.639 85.458,160.693 80.519,160.693 80.519,160.705 78.842,162.382 78.842,167.589 78.308,168.123 75.806,168.123 74.924,169.005 74.924,173.647 75.412,174.135
SW1_1 on L1 "L1-SW1_1" (solid, pour order 195): 78.661,189.37 81.455,192.164 84.112,192.164 85.052,191.224 85.052,188.316 88.405,184.963 88.405,178.905 86.398,176.898 83.145,176.898 79.629,176.898 78.943,177.584 78.943,182.601 78.715,182.829 76.057,182.829 75.311,183.576 75.311,188.341 76.34,189.37
SW2_2 on L1 "L1-SW2_2" (solid, pour order 193): 76.53,204.802 84.863,204.802 86.716,202.949 86.716,194.412 85.407,193.103 80.099,193.103 79.642,193.561 79.642,198.171 79.21,198.603 77.127,198.603 76.086,199.644 76.086,204.357
SW1_2 on L1 "L1-SW1_2" (solid, pour order 191): 81.128,218.415 79.616,216.903 79.616,213.618 79.237,213.239 77.361,213.239 76.276,212.153 76.276,206.375 76.556,206.096 81.946,206.096 82.628,206.778 82.628,208.421 83.041,208.833 84.861,208.833 86.271,207.424 86.271,206.605 86.915,205.962 90.794,205.962 91.421,206.589 91.421,209.055 89.935,210.541 89.027,210.541 87.516,212.052 87.516,217.018 86.119,218.415
SW2 on L1 "SW2_L01_P165" (solid, pour order 165): 88.786,226.099 75.077,226.099 73.698,227.457 73.698,233.323 93.442,233.323 93.442,226.099
SW1 on L1 "SW1_L01_P163" (solid, remove dead copper, pour order 163): 88.328,245.2 74.78,245.2 73.662,244.056 73.662,237.96 93.442,237.96 93.442,245.2
no net on L1 "L1-No Net" (solid, pour order 159): 92.507,97.142
0.85V@40A_INA on L1 "0.85V@40A_INA_L01_P150" (solid, pour order 150): 93.832,226.109 93.832,233.306 97.534,233.306 97.862,232.978 113.243,232.978 113.243,238.214 97.767,238.214 97.5,237.947 93.832,237.947 93.832,245.2 117.137,245.2 117.137,226.109
eMMC_GND on L1 "L1-eMMC_GND" (solid, pour order 147): 112.801,233.236 112.8,233.237 98.128,233.237 97.698,233.667 97.684,233.654 73.698,233.654 73.698,237.566 73.711,237.579 97.621,237.579 98.031,237.989 98.032,237.989 112.877,237.989 112.878,237.989 112.878,233.234
0.85V@40A_INA on L1 "0.85V@40A_INA_L01_P113" (solid, pour order 113): 130.202,304.332 127.457,301.587 127.457,290.055 130.149,287.363 137.2,287.363 137.746,287.91 137.735,287.92 137.735,303.785 137.189,304.332
US+_Vcc_PS_IntFp on L1 "US+_VCC_PS_INTFP_L01_P099" (solid, pour order 99): 145.706,304.356 148.104,301.958 148.104,289.481 146.012,287.388 138.648,287.388 138.102,287.934 138.112,287.945 138.112,303.81 138.659,304.356
AGND_2 on L1 "AGND_2_L01_P134" (solid, remove dead copper, pour order 134): 58.433,213.225 68.437,213.225 68.437,199.489 59.212,199.489 56.667,202.034 56.667,211.46
eMMC_GND on L7(PWR/GND) "EMMC_GND_L07_P259" (solid, pour order 259): 25.865,150.02 359.494,150.02 359.494,499.397 25.865,499.397
US+_Vcc_PS_IntFp on L7(PWR/GND) "US+_VCC_PS_INTFP_L07_P100" (solid, pour order 100): 183.397,310.539 184.397,309.539 184.397,295.539 176.309,287.452 153.022,287.452 138.532,287.452 138.102,287.881 138.102,305.501 143.141,310.539
3V3_RAIL on L7(PWR/GND) "L7(PWR/GND)-3V3_RAIL" (solid, pour order 255): 112.573,190.82 111.872,190.119 102.243,190.119 99.2,187.076 99.2,183.629 100.419,182.41 114.783,182.41 115.557,181.635 115.557,163.36 119.215,159.702 127.203,159.702 139.268,171.767 139.268,196.139 164.376,221.247 222.872,221.247 272.682,271.056 290.906,271.056 306.794,286.944 306.794,350.291 314.642,358.14 314.642,390.233 302.438,402.438 169.887,402.438 160.692,411.632 53.708,411.632 30.81,388.734 30.81,368.173 63.41,335.573 134.278,335.573 154.508,355.803 205.664,355.803 224.879,336.588 224.879,298.629 207.669,281.419 186.436,281.419 124.422,219.405 117.399,219.354 96.353,219.354 84.569,231.138 84.569,244.284 90.322,250.038 112.674,250.038 114.579,251.943 114.529,251.993 114.529,311.302 105.156,320.675 87.287,320.675 81.534,326.428 38.5,326.428 32.118,320.046 32.118,199.146 38.91,192.354 38.91,168.532 42.951,164.49 71.285,164.49 73.33,166.535 73.33,180.226 87.744,194.64 111.364,194.64 112.573,193.432
Vout_1_Selector on L7(PWR/GND) "VOUT_1_SELECTOR_L07_P114" (solid, pour order 114): 48.71,171.566 49.56,170.714 50.782,170.714 51.219,171.151 51.219,179.279 48.872,181.626 48.872,183.189 48.133,183.928 48.369,184.163 48.797,184.163 48.581,184.379 47.911,184.379 45.775,182.242 45.775,180.368 48.71,177.432
SW2 on L7(PWR/GND) "SW2_L07_P135" (solid, pour order 135): 88.786,226.099 75.077,226.099 73.698,227.457 73.698,233.323 93.442,233.323 93.442,226.099
SW1 on L7(PWR/GND) "SW1_L07_P139" (solid, remove dead copper, pour order 139): 88.328,245.2 74.78,245.2 73.662,244.056 73.662,237.96 93.442,237.96 93.442,245.2
0.85V@40A_INA on L7(PWR/GND) "0.85V@40A_INA_L07_P148" (solid, pour order 148): 98.514,243.599 121.488,243.599 125.463,247.574 125.463,300.596 129.984,305.118 136.742,305.118 137.719,304.141 137.719,287.35 142.303,282.765 142.303,232.004 137.132,226.832 98.615,226.832 97.942,227.506 97.942,243.027
eMMC_GND on L8 (Plane_GND) "EMMC_GND_L08_P273" (solid, pour order 273): 25.87,150.012 359.499,150.012 359.499,499.389 25.87,499.389
US+_Vcc_PS_IntFp on L8 (Plane_GND) "US+_VCC_PS_INTFP_L08_P098" (solid, pour order 98): 184.397,309.539 184.397,295.539 176.309,287.452 153.022,287.452 138.532,287.452 138.102,287.881 138.102,305.501 142.141,309.539
5V_RAIL on L8 (Plane_GND) "L8 (Plane_GND)-No Net" (solid, pour order 265): 106.762,206.926 93.345,206.926 91.326,204.907 91.326,200.932 93.421,198.836 118.986,198.836 145.39,172.433 210.274,172.433 236.918,199.078 236.918,225.405 234.721,225.405 216.332,243.794 160.071,243.794 131.305,215.029 114.859,215.029 106.769,206.939
0V9@1A_REG3 on L8 (Plane_GND) "L8 (Plane_GND)-0V9@1A_REG3" (solid, pour order 97): 150.203,285.681 152.641,283.243 152.641,280.772 153.492,279.921 154.788,279.921 155.613,280.746 155.613,285.064 153.282,287.395 150.54,287.395 150.203,287.058
0.85V@40A_INA on L8 (Plane_GND) "0.85V@40A_INA_L08_P104" (solid, pour order 104): 98.514,243.599 121.488,243.599 125.463,247.574 125.463,300.596 129.984,305.118 136.742,305.118 137.719,304.141 137.719,287.35 142.303,282.765 142.303,232.004 137.132,226.832 98.615,226.832 97.942,227.506 97.942,243.027
eMMC_GND on L6 (PWR/GND) "EMMC_GND_L06_P277" (solid, remove dead copper, pour order 277): 25.87,150.012 359.499,150.012 359.499,499.389 25.87,499.389
US+_Vcc_PS_DDR_504 on L6 (PWR/GND) "US+_VCC_PS_DDR_504_L06_P106" (solid, pour order 106): 181.397,311.539 181.397,314.539 182.909,316.052 185.433,316.052 185.737,315.845 190.59,315.845 192.492,313.944 193.822,313.944 195.929,311.837 195.929,310.267 195.184,309.522 193.352,309.522 191.076,311.798 185.229,311.798 184.459,311.027 181.884,311.027 181.884,311.052
CSP on L6 (PWR/GND) "L6 (PWR/GND)-CSP" (solid, pour order 275): 36.83,235.496 43.193,235.496 49.835,228.854 49.835,202.349 49.136,201.651 44.228,201.651 42.634,203.245 42.634,224.104 35.573,231.166 35.573,234.239
RAM_Vcc1V2 on L9 (PWR/GND) "L9 (PWR/GND)-RAM_Vcc1V2" (solid, pour order 281): 168.383,287.344 168.383,290.919 169.004,291.539 176.973,291.539 179.214,293.781 179.214,303.068 177.965,304.317 177.965,308.994 177.905,309.054 176.912,309.054 175.397,307.539 175.397,295.539 174.397,294.539 167.397,294.539 165.95,295.986 161.915,295.986 161.468,295.539 161.62,295.387 161.662,288.579 160.426,287.344 160.426,228.549 122.517,190.64 122.517,178.689 119.875,176.048 102.984,176.048 97.701,170.764 97.701,167.411 99.936,165.176 131.623,165.176 180.442,213.995 180.442,245.478 202.594,267.631 202.594,278.057 216.421,291.884 216.421,340.462 210.642,346.24 160.845,346.24 153.314,338.709 153.314,328.981 160.426,321.869 188.337,321.869 193.314,316.892 193.256,316.834 193.256,284.607 178.613,269.964 168.432,269.964 167.246,271.488 167.246,277.553 168.453,278.76 168.453,287.274
FPGA_Vcc_HD on L9 (PWR/GND) "FPGA_VCC_HD_L09_P103" (solid, pour order 103): 172.397,315.539 173.397,314.539 173.397,313.539 172.397,312.539 172.397,311.539 170.397,311.539 169.397,310.539 169.397,304.539 170.397,303.539 170.397,297.539 169.911,297.053 164.883,297.053 163.397,298.539 159.207,298.539 158.919,298.828 158.919,302.717 159.741,303.539 164.397,303.539 166.397,305.539 166.397,312.539 169.397,315.539
Vout_2_Selector on L9 (PWR/GND) "L9 (PWR/GND)-Vout_2_Selector" (solid, pour order 237): 48.73,184.339 48.729,180.589 49.654,179.663 50.529,179.663 51.194,180.328 51.194,188.436 48.98,190.649 48.98,193.68 48.677,193.983 47.99,193.983 46.284,192.277 46.284,189.77 48.73,187.325
PWR_OUT_20V on L9 (PWR/GND) "PWR_OUT_20V_L09_P167" (solid, pour order 167): 79.121,258.534 86.487,258.534 88.341,256.68 88.341,156.502 55.689,156.502 55.689,240.974 74.155,258.534
no net on L9 (PWR/GND) "NONET_L09_P145" (solid, pour order 145): 60.856,45.86
eMMC_GND on L10 (PWR/GND) "EMMC_GND_L10_P109" (solid, remove dead copper, pour order 109): 25.87,150.012 359.499,150.012 359.499,499.389 25.87,499.389
0V9@1A_REG3 on L10 (PWR/GND) "L10 (PWR/GND)-No Net" (solid, pour order 107): 158.064,296.05 156.223,294.208 156.223,289.56 152.133,285.471 151.257,285.471 150.431,286.296 150.431,287.376 153.302,290.246 153.302,294.754 156.718,298.171 158.077,298.171 167.653,298.171 169.901,295.923 171.839,295.923 172.093,296.177 175.76,296.177 176.397,295.539 176.397,294.539 165.397,294.539 163.887,296.05
FPGA_Vcc_HD on L10 (PWR/GND) "FPGA_VCC_HD_L10_P108" (solid, pour order 108): 186.023,304.851 188.62,304.851 189.154,304.317 189.154,298.782 189.686,298.25 189.686,295.829 188.747,294.89 188.747,293.357 185.572,290.182 182.27,290.182 182.067,290.385 182.067,291.808 184.01,293.751 184.01,302.838
3.3V_PS_Config on L10 (PWR/GND) "3.3V_PS_CONFIG_L10_P102" (solid, pour order 102): 165.557,315.862 166.637,314.782 166.637,309.004 167.615,308.026 174.91,308.026 175.793,307.143 175.793,305.13 165.037,305.13 162.826,307.341 156.743,307.341 156.743,312.423 160.391,312.423 163.83,315.862
1V8@0.5A_ADC_filtered on L10 (PWR/GND) "1V8@0.5A_ADC_FILTERED_L10_P101" (solid, pour order 101): 170.129,298.272 170.129,297.437 171.027,296.539 175.855,296.539 176.847,295.546 176.847,288.442 174.282,285.877 154.432,285.877 152.514,283.959 152.514,282.283 152.921,281.876 169.202,281.876 193.18,281.876 203.429,292.125 203.429,311.147 202.308,312.268 199.887,312.268 198.73,311.11 198.73,294.792 191.071,287.134 181.576,287.134 179.921,288.789 179.921,296.215 182.397,298.691 182.397,300.539 182.397,307.048 179.393,310.052 177.324,310.052 176.987,309.715 176.987,309.172 180.397,305.763 180.397,301.644 177.749,298.996 170.854,298.996
no net on L2 (GND) "NONET_L02_P136" (solid, remove dead copper, pour order 136): 216.165,276.488 216.165,286.209 231.974,286.209 231.974,276.984 230.962,275.972 216.681,275.972
no net on L2 (GND) "NONET_L02_P115" (solid, remove dead copper, pour order 115): 174.608,280.136 174.555,280.189 174.555,291.295 189.304,291.295 189.307,291.298 189.307,280.136
eMMC_GND on L16 "L16-No Net" (solid, pour order 149): 112.814,233.236 112.813,233.237 98.141,233.237 97.71,233.667 97.696,233.654 73.71,233.654 73.71,237.566 73.723,237.579 97.634,237.579 98.044,237.989 112.89,237.989 112.89,233.234
V_PoE+ on L14 (Sign) "L14 (Sign)-V_PoE+" (solid, pour order 207): 49.6,234.95 55.334,229.216 55.334,219.532 47.324,211.522 31.861,211.522 26.619,216.764 26.619,233.705 27.864,234.95
CSN on L12 (Sign) "L12 (Sign)-CSN" (solid, pour order 211): 41.567,193.065 47.899,186.734 51.083,186.734 51.349,187 51.349,190.07 46.736,194.683 46.736,207.893 46.336,208.293 44.302,208.293 41.567,205.557
eMMC_GND on L13 (GND) "EMMC_GND_L13_P110" (solid, pour order 110): 25.87,150.012 359.499,150.012 359.499,499.389 25.87,499.389
eMMC_GND on L4 (GND) "EMMC_GND_L04_P111" (solid, pour order 111): 25.87,150.012 359.499,150.012 359.499,499.389 25.87,499.389
eMMC_GND on L15 (GND) "EMMC_GND_L15_P112" (solid, pour order 112): 25.87,150.012 359.499,150.012 359.499,499.389 25.87,499.389
RAM_DDR4_VTT on L5 (Sign) "L5 (Sign)-RAM_DDR4_VTT" (solid, pour order 283): 150.244,350.898 150.425,351.079 157.856,351.079 159.956,348.979 179.167,348.979 180.048,348.098 180.048,346.265 179.199,345.417 159.258,345.417 158.737,344.896 158.737,333.997 157.204,332.464 155.766,332.464 154.407,333.823 154.407,345.503 152.552,347.358 150.832,347.358 150.244,347.945

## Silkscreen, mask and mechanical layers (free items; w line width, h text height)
Top Overlay:
  text "0.85V 40A" at 102.387,243.332 h2
  text "12V 8A" at 106.648,211.722 h2
  text "5V 10A" at 104.902,195.707 h2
